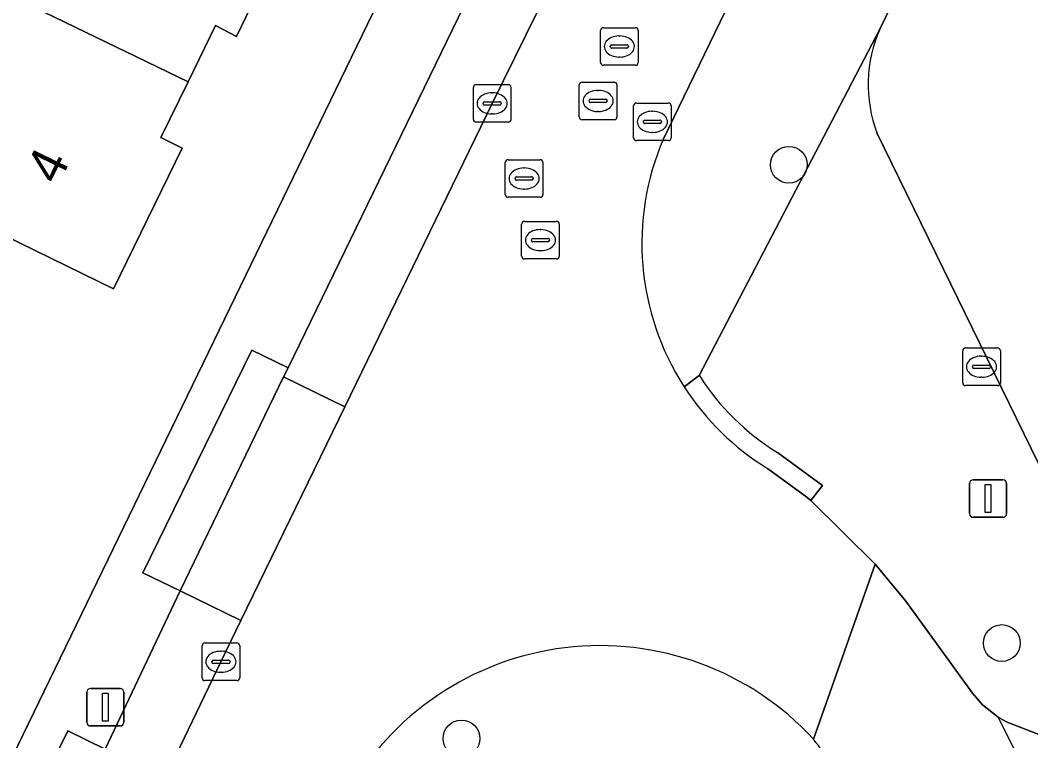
# Model space of a CAD drawing. Extents: x 160455 to 162082, y 388339 to 389736.
# Drawn here: x 160679.51 to 160706.38, y 388927.38 to 388946.54 of the extents above; entities that cross this region are included whole.
import ezdxf

# ---------------------------------------------------------------- set-up
doc = ezdxf.new("R2010")
doc.units = 0
for name, color, linetype in [('IMGEO_Boom', 7, 'Continuous'), ('IMGEO_Erf', 7, 'Continuous'), ('IMGEO_Kolk', 7, 'Continuous'), ('IMGEO_Lichtmast', 7, 'Continuous'), ('IMGEO_Pand', 7, 'Continuous'), ('IMGEO_Pand_nummerreeks', 7, 'Continuous'), ('IMGEO_Parkeervlak_open', 7, 'Continuous'), ('IMGEO_Rijbaan_lokaal_gesloten', 7, 'Continuous'), ('IMGEO_Rijbaan_lokaal_open', 7, 'Continuous'), ('IMGEO_Rioolput', 7, 'Continuous'), ('IMGEO_Voetpad_open', 7, 'Continuous')]:
    doc.layers.add(name, color=color, linetype=linetype)

msp = doc.modelspace()

# ---------------------------------------------------------------- linework, layer by layer
at = {"layer": 'IMGEO_Boom'}
for centre in [(160699.949, 388942.7), (160705.612, 388929.981), (160691.242, 388927.443)]:
    msp.add_circle(centre, 0.489, dxfattribs=at)
at = {"layer": 'IMGEO_Erf'}
for points in [[(160729.207, 389001.634), (160728.414, 389000), (160702.377, 388946.323)], [(160657.921, 388890.507), (160660.482, 388891.731), (160661.527, 388892.231), (160663.339, 388894.117), (160675.312, 388918.745), (160667.999, 388922.239), (160669.423, 388925.093), (160666.641, 388926.482), (160667.999, 388929.204), (160678.026, 388924.35), (160691.138, 388951.382), (160704.109, 388978.111)], [(160693.08, 388966.86), (160694.88, 388965.989), (160693.07, 388962.225), (160692.502, 388962.498), (160691.781, 388961.017), (160691.061, 388959.537), (160691.628, 388959.263), (160689.806, 388955.5), (160685.274, 388957.702), (160683.886, 388954.841), (160682.536, 388952.059), (160687.072, 388949.879), (160685.262, 388946.113), (160684.697, 388946.401), (160683.97, 388944.903), (160683.25, 388943.421), (160683.816, 388943.144), (160681.987, 388939.4), (160677.378, 388941.651)], [(160702.295, 388943.534), (160746.543, 388853.042), (160750.115, 388854.798), (160751.768, 388851.437), (160755.566, 388854.723), (160761.578, 388855.902), (160765.312, 388848.254), (160760.001, 388845.647), (160754.69, 388843.04), (160753.115, 388846.244), (160750.513, 388844.965), (160752.505, 388840.773)]]:
    msp.add_lwpolyline(points, dxfattribs=at)
msp.add_arc((160705.734, 388944.829), 3.675, 156.0034, 200.6284, dxfattribs=at)
at = {"layer": 'IMGEO_Kolk'}
for p, q in [((160691.558, 388943.905), (160691.558, 388944.757)), ((160691.633, 388944.831), (160692.485, 388944.831)), ((160692.559, 388944.757), (160692.559, 388943.905)), ((160692.046, 388944.611), (160692.071, 388944.611)), ((160691.817, 388944.325), (160691.817, 388944.337)), ((160692.255, 388944.288), (160691.857, 388944.288)), ((160691.86, 388944.374), (160692.258, 388944.374)), ((160692.301, 388944.337), (160692.301, 388944.325)), ((160692.069, 388944.051), (160692.044, 388944.051)), ((160692.485, 388943.831), (160691.633, 388943.831)), ((160704.573, 388936.902), (160704.573, 388937.754)), ((160704.648, 388937.828), (160705.5, 388937.828)), ((160705.574, 388937.754), (160705.574, 388936.902)), ((160705.061, 388937.608), (160705.086, 388937.608)), ((160704.832, 388937.322), (160704.832, 388937.334)), ((160705.27, 388937.285), (160704.872, 388937.285)), ((160704.875, 388937.371), (160705.273, 388937.371)), ((160705.316, 388937.334), (160705.316, 388937.322)), ((160705.084, 388937.048), (160705.059, 388937.048)), ((160705.5, 388936.828), (160704.648, 388936.828)), ((160684.344, 388929.057), (160684.344, 388929.909)), ((160684.419, 388929.983), (160685.271, 388929.983)), ((160685.345, 388929.909), (160685.345, 388929.057)), ((160684.832, 388929.763), (160684.857, 388929.763)), ((160684.603, 388929.477), (160684.603, 388929.489)), ((160685.041, 388929.44), (160684.643, 388929.44)), ((160684.646, 388929.526), (160685.044, 388929.526)), ((160685.087, 388929.489), (160685.087, 388929.477)), ((160684.855, 388929.203), (160684.83, 388929.203)), ((160685.271, 388928.983), (160684.419, 388928.983))]:
    msp.add_line(p, q, dxfattribs=at)
for points in [[(160691.558, 388943.905), (160691.558, 388944.757)], [(160691.633, 388944.831), (160692.485, 388944.831)], [(160692.559, 388944.757), (160692.559, 388943.905)], [(160692.485, 388943.831), (160691.633, 388943.831)], [(160704.573, 388936.902), (160704.573, 388937.754)], [(160704.648, 388937.828), (160705.5, 388937.828)], [(160705.574, 388937.754), (160705.574, 388936.902)], [(160705.5, 388936.828), (160704.648, 388936.828)], [(160684.344, 388929.057), (160684.344, 388929.909)], [(160684.419, 388929.983), (160685.271, 388929.983)], [(160685.345, 388929.909), (160685.345, 388929.057)], [(160685.271, 388928.983), (160684.419, 388928.983)]]:
    msp.add_lwpolyline(points, dxfattribs=at)
for centre, radius, start, end in [((160691.635, 388944.755), 0.0765, 91.552, 178.448), ((160691.635, 388944.755), 0.0765, 91.552, 178.448), ((160692.483, 388944.755), 0.0765, 1.552, 88.448), ((160692.483, 388944.755), 0.0765, 1.552, 88.448), ((160691.857, 388944.334), 0.0403, 85.8775, 175.7526), ((160691.854, 388944.324), 0.0366, 178.938, 274.7102), ((160692.258, 388944.331), 0.043, 264.8664, 352.4533), ((160692.262, 388944.336), 0.0386, 1.7309, 96.639), ((160691.635, 388943.907), 0.0765, 181.552, 268.448), ((160691.635, 388943.907), 0.0765, 181.552, 268.448), ((160692.483, 388943.907), 0.0765, 271.552, 358.448), ((160692.483, 388943.907), 0.0765, 271.552, 358.448), ((160704.65, 388937.752), 0.0765, 91.552, 178.448), ((160704.65, 388937.752), 0.0765, 91.552, 178.448), ((160705.498, 388937.752), 0.0765, 1.552, 88.448), ((160705.498, 388937.752), 0.0765, 1.552, 88.448), ((160704.872, 388937.331), 0.0403, 85.8775, 175.7526), ((160704.869, 388937.321), 0.0366, 178.938, 274.7102), ((160705.273, 388937.328), 0.043, 264.8664, 352.4533), ((160705.277, 388937.333), 0.0386, 1.7309, 96.639), ((160704.65, 388936.904), 0.0765, 181.552, 268.448), ((160704.65, 388936.904), 0.0765, 181.552, 268.448), ((160705.498, 388936.904), 0.0765, 271.552, 358.448), ((160705.498, 388936.904), 0.0765, 271.552, 358.448), ((160684.421, 388929.907), 0.0765, 91.552, 178.448), ((160684.421, 388929.907), 0.0765, 91.552, 178.448), ((160685.269, 388929.907), 0.0765, 1.552, 88.448), ((160685.269, 388929.907), 0.0765, 1.552, 88.448), ((160684.643, 388929.486), 0.0403, 85.8775, 175.7526), ((160684.64, 388929.476), 0.0366, 178.938, 274.7102), ((160685.044, 388929.483), 0.043, 264.8664, 352.4533), ((160685.048, 388929.488), 0.0386, 1.7309, 96.639), ((160684.421, 388929.059), 0.0765, 181.552, 268.448), ((160684.421, 388929.059), 0.0765, 181.552, 268.448), ((160685.269, 388929.059), 0.0765, 271.552, 358.448), ((160685.269, 388929.059), 0.0765, 271.552, 358.448)]:
    msp.add_arc(centre, radius, start, end, dxfattribs=at)
for centre, major_axis, ratio, start_param, end_param in [((160692.045, 388944.331), (-0.387, 0.002), 0.722429, 4.712389, 7.853982), ((160692.07, 388944.331), (-0.39, 0.002), 0.717154, 1.570796, 4.712389), ((160705.06, 388937.328), (-0.387, 0.002), 0.722429, 4.712389, 7.853982), ((160705.085, 388937.328), (-0.39, 0.002), 0.717154, 1.570796, 4.712389), ((160684.831, 388929.483), (-0.387, 0.002), 0.722429, 4.712389, 7.853982), ((160684.856, 388929.483), (-0.39, 0.002), 0.717154, 1.570796, 4.712389)]:
    msp.add_ellipse(centre, major_axis=major_axis, ratio=ratio, start_param=start_param, end_param=end_param, dxfattribs=at)
at = {"layer": 'IMGEO_Lichtmast'}
for p, q in [((160704.752, 388933.424), (160704.752, 388934.224)), ((160704.752, 388934.224), (160704.752, 388933.424)), ((160704.852, 388934.324), (160705.642, 388934.324)), ((160705.642, 388934.324), (160704.852, 388934.324)), ((160705.742, 388934.224), (160705.742, 388933.424)), ((160705.742, 388933.424), (160705.742, 388934.224)), ((160705.642, 388933.324), (160704.852, 388933.324)), ((160704.852, 388933.324), (160705.642, 388933.324)), ((160681.275, 388927.875), (160681.275, 388928.675)), ((160681.275, 388928.675), (160681.275, 388927.875)), ((160681.375, 388928.775), (160682.165, 388928.775)), ((160682.165, 388928.775), (160681.375, 388928.775)), ((160682.265, 388928.675), (160682.265, 388927.875)), ((160682.265, 388927.875), (160682.265, 388928.675)), ((160682.165, 388927.775), (160681.375, 388927.775)), ((160681.375, 388927.775), (160682.165, 388927.775))]:
    msp.add_line(p, q, dxfattribs=at)
for points in [[(160705.172, 388934.199), (160705.322, 388934.199), (160705.322, 388933.449), (160705.172, 388933.449), (160705.172, 388934.199)], [(160681.695, 388928.65), (160681.845, 388928.65), (160681.845, 388927.9), (160681.695, 388927.9), (160681.695, 388928.65)]]:
    msp.add_lwpolyline(points, dxfattribs=at)
for centre, start, end in [((160704.852, 388934.224), 90, 180), ((160704.852, 388934.224), 90, 180), ((160705.642, 388934.224), 0, 90), ((160705.642, 388934.224), 360, 90), ((160704.852, 388933.424), 180, 270), ((160704.852, 388933.424), 180, 270), ((160705.642, 388933.424), 270, 0), ((160705.642, 388933.424), 270, 0), ((160681.375, 388928.675), 90, 180), ((160681.375, 388928.675), 90, 180), ((160682.165, 388928.675), 0, 90), ((160682.165, 388928.675), 360, 90), ((160681.375, 388927.875), 180, 270), ((160681.375, 388927.875), 180, 270), ((160682.165, 388927.875), 270, 0), ((160682.165, 388927.875), 270, 0)]:
    msp.add_arc(centre, 0.1, start, end, dxfattribs=at)
at = {"layer": 'IMGEO_Pand'}
for points in [[(160676.722, 388958.308), (160675.233, 388955.238), (160675.969, 388954.881), (160673.574, 388949.941), (160683.97, 388944.903), (160684.697, 388946.401), (160685.262, 388946.113), (160687.072, 388949.879), (160682.536, 388952.059), (160683.886, 388954.841)], [(160676.02, 388938.842), (160677.378, 388941.651), (160681.987, 388939.4), (160683.816, 388943.144), (160683.25, 388943.421), (160683.97, 388944.903), (160673.574, 388949.941), (160671.191, 388945.025), (160670.455, 388945.381), (160668.962, 388942.301)]]:
    msp.add_lwpolyline(points, close=True, dxfattribs=at)
at = {"layer": 'IMGEO_Parkeervlak_open'}
for points in [[(160692.061, 388944.331), (160693.247, 388946.742), (160691.606, 388947.55), (160686.63, 388937.298), (160686.513, 388937.056), (160688.141, 388936.264)], [(160688.141, 388936.264), (160686.513, 388937.056), (160683.757, 388931.366), (160685.378, 388930.578)], [(160685.378, 388930.578), (160683.757, 388931.366), (160681.762, 388927.162), (160681.271, 388926.162), (160682.875, 388925.384), (160683.092, 388925.831), (160683.176, 388926.01), (160683.336, 388926.342), (160684.846, 388929.483)]]:
    msp.add_lwpolyline(points, close=True, dxfattribs=at)
msp.add_lwpolyline([(160707.629, 388927.15), (160705.759, 388927.875), (160705.639, 388927.943), (160705.518, 388928.008), (160706.228, 388926.593), (160707.087, 388924.788), (160708.698, 388925.555), (160708.463, 388926.045), (160708.184, 388926.626)], dxfattribs=at)
at = {"layer": 'IMGEO_Rijbaan_lokaal_gesloten'}
msp.add_lwpolyline([(160725.78, 388886.522), (160722.954, 388892.3), (160717.809, 388902.817), (160715.22, 388908.111), (160715.034, 388908.492), (160709.928, 388918.955), (160707.289, 388924.364), (160707.087, 388924.788), (160706.228, 388926.593), (160705.518, 388928.008), (160705.103, 388928.339), (160704.831, 388928.646), (160703.057, 388931.096), (160702.245, 388932.077), (160700.602, 388927.427)], dxfattribs=at)
msp.add_arc((160696.15, 388923.847), 5.713, 21.0914, 38.8024, dxfattribs=at)
at = {"layer": 'IMGEO_Rijbaan_lokaal_open'}
for points in [[(160696.612, 388943.387), (160698.937, 388948.196), (160699.018, 388948.363), (160695.01, 388950.344), (160694.6, 388949.491), (160693.247, 388946.742), (160692.061, 388944.331), (160688.141, 388936.264), (160685.378, 388930.578), (160684.846, 388929.483), (160683.336, 388926.342), (160687.359, 388924.247), (160687.787, 388925.075), (160688.161, 388925.909)], [(160700.602, 388927.427), (160702.245, 388932.077), (160700.533, 388933.771), (160700.43, 388933.859), (160699.385, 388934.622)]]:
    msp.add_lwpolyline(points, dxfattribs=at)
for centre, radius, start, end in [((160703.056, 388940.609), 7.017, 156.675, 212.9012), ((160703.032, 388940.568), 6.975, 212.7244, 238.4746), ((160694.928, 388922.191), 7.721, 42.7017, 151.2116)]:
    msp.add_arc(centre, radius, start, end, dxfattribs=at)
at = {"layer": 'IMGEO_Rioolput'}
for p, q in [((160694.941, 388945.418), (160694.941, 388946.27)), ((160695.016, 388946.344), (160695.868, 388946.344)), ((160695.942, 388946.27), (160695.942, 388945.418)), ((160695.429, 388946.124), (160695.454, 388946.124)), ((160695.2, 388945.838), (160695.2, 388945.85)), ((160695.638, 388945.801), (160695.24, 388945.801)), ((160695.243, 388945.887), (160695.641, 388945.887)), ((160695.684, 388945.85), (160695.684, 388945.838)), ((160695.452, 388945.564), (160695.427, 388945.564)), ((160695.868, 388945.344), (160695.016, 388945.344)), ((160694.375, 388943.971), (160694.375, 388944.823)), ((160694.45, 388944.897), (160695.302, 388944.897)), ((160694.863, 388944.677), (160694.888, 388944.677)), ((160695.376, 388944.823), (160695.376, 388943.971)), ((160694.634, 388944.391), (160694.634, 388944.403)), ((160694.677, 388944.44), (160695.075, 388944.44)), ((160695.118, 388944.403), (160695.118, 388944.391)), ((160695.072, 388944.354), (160694.674, 388944.354)), ((160694.886, 388944.117), (160694.861, 388944.117)), ((160695.819, 388943.415), (160695.819, 388944.267)), ((160695.894, 388944.341), (160696.746, 388944.341)), ((160696.307, 388944.121), (160696.332, 388944.121)), ((160696.82, 388944.267), (160696.82, 388943.415)), ((160695.302, 388943.897), (160694.45, 388943.897)), ((160696.078, 388943.835), (160696.078, 388943.847)), ((160696.121, 388943.884), (160696.519, 388943.884)), ((160696.562, 388943.847), (160696.562, 388943.835)), ((160696.516, 388943.798), (160696.118, 388943.798)), ((160696.746, 388943.341), (160695.894, 388943.341)), ((160696.33, 388943.561), (160696.305, 388943.561)), ((160692.482, 388942.834), (160693.334, 388942.834)), ((160692.407, 388941.908), (160692.407, 388942.76)), ((160692.895, 388942.614), (160692.92, 388942.614)), ((160693.408, 388942.76), (160693.408, 388941.908)), ((160692.666, 388942.328), (160692.666, 388942.34)), ((160693.104, 388942.291), (160692.706, 388942.291)), ((160692.709, 388942.377), (160693.107, 388942.377)), ((160693.15, 388942.34), (160693.15, 388942.328)), ((160692.918, 388942.054), (160692.893, 388942.054)), ((160693.334, 388941.834), (160692.482, 388941.834)), ((160692.918, 388941.195), (160693.77, 388941.195)), ((160692.843, 388940.269), (160692.843, 388941.121)), ((160693.331, 388940.975), (160693.356, 388940.975)), ((160693.844, 388941.121), (160693.844, 388940.269)), ((160693.102, 388940.689), (160693.102, 388940.701)), ((160693.54, 388940.652), (160693.142, 388940.652)), ((160693.145, 388940.738), (160693.543, 388940.738)), ((160693.586, 388940.701), (160693.586, 388940.689)), ((160693.354, 388940.415), (160693.329, 388940.415)), ((160693.77, 388940.195), (160692.918, 388940.195))]:
    msp.add_line(p, q, dxfattribs=at)
for points in [[(160694.941, 388945.418), (160694.941, 388946.27)], [(160695.016, 388946.344), (160695.868, 388946.344)], [(160695.942, 388946.27), (160695.942, 388945.418)], [(160695.868, 388945.344), (160695.016, 388945.344)], [(160694.375, 388943.971), (160694.375, 388944.823)], [(160694.45, 388944.897), (160695.302, 388944.897)], [(160695.376, 388944.823), (160695.376, 388943.971)], [(160695.819, 388943.415), (160695.819, 388944.267)], [(160695.894, 388944.341), (160696.746, 388944.341)], [(160696.82, 388944.267), (160696.82, 388943.415)], [(160695.302, 388943.897), (160694.45, 388943.897)], [(160696.746, 388943.341), (160695.894, 388943.341)], [(160692.482, 388942.834), (160693.334, 388942.834)], [(160692.407, 388941.908), (160692.407, 388942.76)], [(160693.408, 388942.76), (160693.408, 388941.908)], [(160693.334, 388941.834), (160692.482, 388941.834)], [(160692.918, 388941.195), (160693.77, 388941.195)], [(160692.843, 388940.269), (160692.843, 388941.121)], [(160693.844, 388941.121), (160693.844, 388940.269)], [(160693.77, 388940.195), (160692.918, 388940.195)]]:
    msp.add_lwpolyline(points, dxfattribs=at)
for centre, radius, start, end in [((160695.018, 388946.268), 0.0765, 91.552, 178.448), ((160695.018, 388946.268), 0.0765, 91.552, 178.448), ((160695.866, 388946.268), 0.0765, 1.552, 88.448), ((160695.866, 388946.268), 0.0765, 1.552, 88.448), ((160695.24, 388945.847), 0.0403, 85.8775, 175.7526), ((160695.237, 388945.837), 0.0366, 178.938, 274.7102), ((160695.641, 388945.844), 0.043, 264.8664, 352.4533), ((160695.645, 388945.849), 0.0386, 1.7309, 96.639), ((160695.018, 388945.42), 0.0765, 181.552, 268.448), ((160695.018, 388945.42), 0.0765, 181.552, 268.448), ((160695.866, 388945.42), 0.0765, 271.552, 358.448), ((160695.866, 388945.42), 0.0765, 271.552, 358.448), ((160694.452, 388944.821), 0.0765, 91.552, 178.448), ((160694.452, 388944.821), 0.0765, 91.552, 178.448), ((160695.3, 388944.821), 0.0765, 1.552, 88.448), ((160695.3, 388944.821), 0.0765, 1.552, 88.448), ((160694.674, 388944.4), 0.0403, 85.8775, 175.7526), ((160694.671, 388944.39), 0.0366, 178.938, 274.7102), ((160695.075, 388944.397), 0.043, 264.8664, 352.4533), ((160695.079, 388944.402), 0.0386, 1.7309, 96.639), ((160695.896, 388944.265), 0.0765, 91.552, 178.448), ((160695.896, 388944.265), 0.0765, 91.552, 178.448), ((160696.744, 388944.265), 0.0765, 1.552, 88.448), ((160696.744, 388944.265), 0.0765, 1.552, 88.448), ((160694.452, 388943.973), 0.0765, 181.552, 268.448), ((160694.452, 388943.973), 0.0765, 181.552, 268.448), ((160695.3, 388943.973), 0.0765, 271.552, 358.448), ((160695.3, 388943.973), 0.0765, 271.552, 358.448), ((160696.118, 388943.844), 0.0403, 85.8775, 175.7526), ((160696.523, 388943.846), 0.0386, 1.7309, 96.639), ((160696.115, 388943.834), 0.0366, 178.938, 274.7102), ((160696.519, 388943.841), 0.043, 264.8664, 352.4533), ((160695.896, 388943.417), 0.0765, 181.552, 268.448), ((160695.896, 388943.417), 0.0765, 181.552, 268.448), ((160696.744, 388943.417), 0.0765, 271.552, 358.448), ((160696.744, 388943.417), 0.0765, 271.552, 358.448), ((160692.484, 388942.758), 0.0765, 91.552, 178.448), ((160692.484, 388942.758), 0.0765, 91.552, 178.448), ((160693.332, 388942.758), 0.0765, 1.552, 88.448), ((160693.332, 388942.758), 0.0765, 1.552, 88.448), ((160692.706, 388942.337), 0.0403, 85.8775, 175.7526), ((160692.703, 388942.327), 0.0366, 178.938, 274.7102), ((160693.107, 388942.334), 0.043, 264.8664, 352.4533), ((160693.111, 388942.339), 0.0386, 1.7309, 96.639), ((160692.484, 388941.91), 0.0765, 181.552, 268.448), ((160692.484, 388941.91), 0.0765, 181.552, 268.448), ((160693.332, 388941.91), 0.0765, 271.552, 358.448), ((160693.332, 388941.91), 0.0765, 271.552, 358.448), ((160692.92, 388941.119), 0.0765, 91.552, 178.448), ((160692.92, 388941.119), 0.0765, 91.552, 178.448), ((160693.768, 388941.119), 0.0765, 1.552, 88.448), ((160693.768, 388941.119), 0.0765, 1.552, 88.448), ((160693.142, 388940.698), 0.0403, 85.8775, 175.7526), ((160693.139, 388940.688), 0.0366, 178.938, 274.7102), ((160693.543, 388940.695), 0.043, 264.8664, 352.4533), ((160693.547, 388940.7), 0.0386, 1.7309, 96.639), ((160692.92, 388940.271), 0.0765, 181.552, 268.448), ((160692.92, 388940.271), 0.0765, 181.552, 268.448), ((160693.768, 388940.271), 0.0765, 271.552, 358.448), ((160693.768, 388940.271), 0.0765, 271.552, 358.448)]:
    msp.add_arc(centre, radius, start, end, dxfattribs=at)
for centre, major_axis, ratio, start_param, end_param in [((160695.428, 388945.844), (-0.387, 0.002), 0.722429, 4.712389, 7.853982), ((160695.453, 388945.844), (-0.39, 0.002), 0.717154, 1.570796, 4.712389), ((160694.862, 388944.397), (-0.387, 0.002), 0.722429, 4.712389, 7.853982), ((160694.887, 388944.397), (-0.39, 0.002), 0.717154, 1.570796, 4.712389), ((160696.306, 388943.841), (-0.387, 0.002), 0.722429, 4.712389, 7.853982), ((160696.331, 388943.841), (-0.39, 0.002), 0.717154, 1.570796, 4.712389), ((160692.894, 388942.334), (-0.387, 0.002), 0.722429, 4.712389, 7.853982), ((160692.919, 388942.334), (-0.39, 0.002), 0.717154, 1.570796, 4.712389), ((160693.33, 388940.695), (-0.387, 0.002), 0.722429, 4.712389, 7.853982), ((160693.355, 388940.695), (-0.39, 0.002), 0.717154, 1.570796, 4.712389)]:
    msp.add_ellipse(centre, major_axis=major_axis, ratio=ratio, start_param=start_param, end_param=end_param, dxfattribs=at)
at = {"layer": 'IMGEO_Voetpad_open'}
for points in [[(160717.954, 389006.662), (160714.723, 389000), (160704.109, 388978.111), (160691.138, 388951.382), (160678.026, 388924.35), (160675.312, 388918.745), (160663.339, 388894.117), (160661.527, 388892.231), (160660.482, 388891.731), (160657.921, 388890.507)], [(160676.337, 388918.613), (160680.775, 388927.647), (160681.762, 388927.162), (160683.757, 388931.366), (160682.769, 388931.85), (160685.666, 388937.77), (160686.63, 388937.298), (160691.606, 388947.55), (160690.618, 388948.034), (160693.849, 388954.635), (160694.843, 388954.148), (160699.037, 388962.811), (160698.049, 388963.295), (160701.64, 388970.632), (160702.597, 388970.163), (160706.047, 388977.185), (160706.937, 388979.099), (160705.949, 388979.583), (160709.933, 388987.723), (160710.888, 388987.255), (160715.085, 388995.868), (160717.091, 389000), (160718.738, 389003.391)], [(160702.377, 388946.323), (160728.414, 389000), (160729.207, 389001.634)], [(160698.937, 388948.196), (160696.612, 388943.387)], [(160697.164, 388936.797), (160697.568, 388937.092), (160702.377, 388946.323)], [(160702.377, 388946.323), (160697.568, 388937.092)], [(160750.513, 388844.965), (160746.543, 388853.042), (160702.295, 388943.534)], [(160697.568, 388937.092), (160697.164, 388936.797)], [(160699.385, 388934.622), (160700.43, 388933.859), (160700.533, 388933.771), (160700.848, 388934.173), (160699.647, 388935.048)], [(160699.647, 388935.048), (160700.848, 388934.173), (160700.533, 388933.771), (160702.245, 388932.077), (160703.057, 388931.096), (160704.831, 388928.646), (160705.103, 388928.339), (160705.518, 388928.008), (160705.639, 388927.943), (160705.759, 388927.875), (160707.629, 388927.15)]]:
    msp.add_lwpolyline(points, dxfattribs=at)
for points in [[(160686.513, 388937.056), (160686.63, 388937.298), (160685.666, 388937.77), (160682.769, 388931.85), (160683.757, 388931.366)], [(160681.271, 388926.162), (160681.762, 388927.162), (160680.775, 388927.647), (160676.337, 388918.613), (160677.324, 388918.128), (160677.783, 388919.062)]]:
    msp.add_lwpolyline(points, close=True, dxfattribs=at)
for centre, radius, start, end in [((160705.734, 388944.829), 3.675, 156.0034, 200.6284), ((160703.056, 388940.609), 7.017, 156.675, 212.9012), ((160703.061, 388940.6), 6.517, 212.5618, 238.411), ((160703.061, 388940.6), 6.517, 212.5618, 238.411), ((160703.032, 388940.568), 6.975, 212.7244, 238.4746), ((160694.928, 388922.191), 7.721, 42.7017, 151.2116), ((160696.15, 388923.847), 5.713, 21.0914, 38.8024)]:
    msp.add_arc(centre, radius, start, end, dxfattribs=at)

# ---------------------------------------------------------------- texts
at = {"layer": 'IMGEO_Pand_nummerreeks'}
msp.add_text('4', height=1, rotation=63.9638, dxfattribs=at).set_placement((160680.517, 388942.131))

doc.saveas('drawing.dxf')
